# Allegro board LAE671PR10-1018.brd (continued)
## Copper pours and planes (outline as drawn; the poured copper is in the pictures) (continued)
B+ on IN2 (solid shape): 295.99,9.2 295.99,6.13 295.89,6.03 294.48,6.03 294.33,6.18 294.33,9.16 294.52,9.35 295.84,9.35
B+ on IN3 (solid shape): 132.33,2.61 132.33,1.62 132.06,1.35 128.11,1.35 127.9,1.56 127.9,2.5 128.16,2.76 132.19,2.76
B+ on IN3 (solid shape): 159.74,2.14 159.74,1.55 159.49,1.3 157.25,1.3 156.86,1.68 156.86,2.14 157.44,2.72 159.16,2.72
B+ on IN3 (solid shape): 91.76,2.89 91.76,1.74 91.31,1.29 86.77,1.29 86.7,1.35 86.59,1.35 86.35,1.59 86.35,2.83 86.7,3.18 91.47,3.18
B+ on IN3 (solid shape): outline of 4465 points within 44.29,13.1 76.23,30.97
B+ on GND3 (solid shape): 224.76,1.91 224.76,1.5 224.64,1.38 223.1,1.38 223,1.48 223,1.83 223.32,2.15 224.51,2.15
B+ on GND3 (solid shape): 268.19,2.21 268.19,1.47 268.09,1.37 266.9,1.37 266.77,1.5 266.77,2.1 266.94,2.26 268.13,2.26
B+ on IN4 (solid shape): 281.58,36.79 281.58,33.93 280.93,33.93 280.72,34.15 280.72,36.74 280.84,36.86 281.51,36.86
B+ on IN4 (solid shape): 281.64,40.29 281.64,39.26 281.53,39.14 280.83,39.14 280.71,39.26 280.71,40.34 280.84,40.47 281.46,40.47
B+ on VCC: 63.39,14 61.61,15.78 61.58,26.43 59.78,28.23 56.05,28.23 54.78,29.5 54.78,39.43 52.34,41.87 52.34,53.17 58.06,53.17 58.97,54.08 58.97,64.27 61.9,67.2 62.06,67.2 62.19,67.32 70.02,67.32 70.03,67.19 70.39,66.88 70.42,42.07 70.42,41.94 71.7,40.66 79.62,40.66 79.97,40.27 79.97,16.79 79.52,16.34 79.51,16.34 77.56,16.34 75.25,14 ; 2 cut-outs
B+ on VCC: 167.1,35.67 163.36,39.41 163.36,52.91 167.54,57.09 170.83,57.09 171.35,56.57 171.36,56.57 171.36,35.67
B+ on VCC: 267.27,3.02 269.11,4.86 275.05,4.86 275.76,5.59 277.51,5.59 279.82,7.91 295.56,7.91 295.99,7.47 295.99,3.27 274.93,3.27 273.68,2.75 273.16,1.5 273.16,1.27 266.88,1.27 266.77,1.37 266.77,2.53
B+_1.0V on TOP (solid shape): 132.1,5.27 132.1,4.55 132.6,4.06 133.46,4.06 133.59,3.93 133.59,3.33 133.49,3.23 131.51,3.23 131.21,3.53 131.21,3.54 131.04,3.71 131.04,5.25 131.21,5.42 131.96,5.42
B+_1.0V on BOTTOM (solid shape): 132.11,5.37 132.11,4.96 132.07,4.92 132.07,4.29 132.29,4.07 132.8,4.07 132.87,4.06 132.95,4.07 133.44,4.07 133.69,4.32 133.69,4.64 133.76,4.72 135.31,4.72 135.4,4.63 135.4,2.91 134.31,1.82 131.1,1.82 130.9,2.03 130.9,3.11 130.62,3.39 129.62,3.39 129.45,3.57 129.45,4.37 129.54,4.47 130.99,4.47 131.2,4.68 131.2,5.31 131.31,5.43 132.05,5.43
B+_3V on TOP (solid shape): 54.44,27.17 54.44,24.88 54.16,24.6 54.16,22.54 53.67,22.06 52.75,22.06 52.64,22.17 52.64,27.26 52.79,27.41 54.2,27.41
B+_3V on BOTTOM (solid shape): 54.37,27.27 54.37,20.89 54.37,20.89 54.37,20.77 54.21,20.61 52.5,20.61 52.44,20.67 52.44,22.11 52.6,22.27 52.6,25.33 52.37,25.56 52.08,25.56 51.82,25.82 51.82,27.28 51.9,27.37 54.27,27.37
B+_5V on TOP (solid shape): 46.27,26.63 46.27,24.99 46.19,24.91 44.93,24.91 44.5,24.48 44.5,21.69 43.59,21.69 43.47,21.8 43.47,23.96 43.35,24.09 42.73,24.09 42.48,24.34 42.48,25.5 43.87,26.89 46,26.89
B+_5V on BOTTOM (solid shape): 46.2,26.28 46.2,24.81 46.09,24.7 44.77,24.7 44.55,24.47 44.55,23.05 44.52,23.02 44.52,21.75 44.43,21.67 43.58,21.67 43.33,21.92 43.33,23.62 43.31,23.64 43.31,23.77 43.13,23.95 42.55,23.95 42.03,24.46 41.67,24.46 41.65,24.47 40.98,24.47 40.91,24.54 40.91,26.02 40.96,26.07 43,26.07 43.21,26.28 43.21,26.5 43.51,26.8 45.68,26.8
B+_AMP on TOP (solid shape): 276.45,6.01 276.45,5.29 276.26,5.1 275.19,5.1 274.95,4.86 274.66,4.86 274.64,4.88 274.64,5.69 274.69,5.74 274.79,5.74 274.85,5.68 274.85,5.52 274.85,5.51 274.85,5.17 274.89,5.13 275.02,5.13 275.08,5.2 275.08,5.44 275.24,5.6 276,5.6 276.16,5.76 276.16,6.02 276.03,6.14 275.33,6.14 275.27,6.2 275.27,6.3 275.33,6.36 276.1,6.36
B+_AMP on BOTTOM (solid shape): outline of 232 points within 267.9,2.57 277.31,14.52
B+_CAM on BOTTOM (solid shape): 282.73,33.38 282.73,30.55 282.01,29.83 281.45,29.83 280.21,28.58 280.21,27.86 280.12,27.77 278.04,27.77 277.92,27.9 277.92,28.66 278.07,28.81 278.77,28.81 280.46,30.5 280.46,30.51 280.8,30.85 280.8,33.43 280.9,33.53 282.58,33.53
B+_CAM_F on BOTTOM (solid shape): 280.24,37.7 280.24,35.46 280.3,35.39 280.28,35.27 280.31,35.14 280.31,33.75 280.15,33.59 280.15,32.65 280.11,32.61 278.73,32.61 278.58,32.77 278.58,34.9 279.23,35.56 279.23,37.8 279.31,37.88 280.06,37.88
BST_1.0V on BOTTOM (solid shape): 135.86,4.62 135.86,3.65 136.16,3.36 136.16,2.09 136.11,2.04 135.59,2.04 135.54,2.09 135.54,4.67 135.6,4.73 135.76,4.73
BST_3V on BOTTOM (solid shape): 54.25,28.36 54.25,27.59 54.2,27.54 51.92,27.54 51.84,27.62 51.84,27.74 52.48,28.38 54.23,28.38
BST_5V on TOP (solid shape): 42.97,27.3 42.97,26.41 42.88,26.32 41.94,26.32 41.72,26.54 41.72,27.49 41.89,27.65 42.62,27.65
BST_5V on BOTTOM (solid shape): 42.97,26.79 42.97,26.39 42.96,26.38 42.96,26.37 42.84,26.25 40.92,26.25 40.87,26.3 40.87,26.44 40.97,26.54 41.58,26.54 41.76,26.72 41.78,26.72 42.01,26.95 42.81,26.95
CHG_BST1 on TOP (solid shape): 65.45,16.83 65.45,16.33 65.32,16.2 64.84,16.2 64.55,15.91 64.55,14.99 64.37,14.8 64.37,14.78 64.31,14.72 64.31,13.66 64.26,13.61 64.17,13.61 64.12,13.67 64.12,15.08 64.22,15.18 64.22,16.21 64.22,16.21 64.22,16.52 64.64,16.94 65.35,16.94
CHG_BST2 on TOP (solid shape): 68.81,12.84 68.81,12.51 68.03,11.73 68.03,11.73 67.82,11.53 66.66,11.53 66.63,11.53 66.47,11.7 65.68,11.7 65.63,11.75 65.63,11.87 65.67,11.91 66.49,11.91 66.68,11.73 67.47,11.73 67.77,12.02 67.77,12.85 67.88,12.97 68.68,12.97
CHG_BST2 on BOTTOM (solid shape): 68.65,13.66 68.65,13.02 68.78,12.89 68.78,12.65 68.65,12.52 67.87,12.52 67.75,12.64 67.75,12.88 67.64,12.99 67.64,13.68 67.73,13.77 68.54,13.77
CHG_DCIN on TOP (solid shape): 62.34,14.46 62.34,14.15 62.16,13.97 61.68,13.97 61.58,13.87 61.58,13.64 61.7,13.52 62.35,13.52 62.41,13.45 62.41,13.35 62.37,13.31 61.52,13.31 61.08,13.75 61.08,14.42 61.27,14.61 62.18,14.61
CHG_LG1 on TOP (solid shape): 66.57,14.93 66.57,14.65 65.92,14.01 65.6,14.01 65.52,13.93 65.52,13.78 65.52,13.77 65.52,13.66 65.47,13.61 65.37,13.61 65.31,13.66 65.31,14.45 65.37,14.51 65.7,14.51 66.22,15.03 66.47,15.03
CHG_LG1 on BOTTOM (solid shape): 63.21,28.28 63.21,26.42 62.98,26.19 62.31,26.19 62.02,26.48 62.02,28.25 62.19,28.42 63.07,28.42
CHG_LG1 on IN2 (solid shape): 63.25,28.37 63.25,27.32 63.04,27.12 62.27,27.12 62.07,27.32 62.07,28.35 62.26,28.54 63.07,28.54
CHG_LG1 on IN2 (solid shape): 67.4,16.16 67.4,15.1 66.12,13.82 65.68,13.82 65.59,13.91 65.59,14.38 66.64,15.43 66.64,16.18 67.39,16.18
CHG_LG2 on TOP (solid shape): 67.56,14.07 67.56,13.84 66.8,13.08 66.8,13.08 66.61,12.89 65.66,12.89 65.62,12.93 65.62,13.08 65.66,13.11 66.52,13.11 66.66,13.26 66.66,13.6 67.02,13.96 67.02,14.03 67.17,14.18 67.45,14.18
CHG_LG2 on BOTTOM (solid shape): 69.69,21.1 69.69,20.71 69.6,20.62 68.2,20.62 68.12,20.7 68.12,21.23 68.23,21.33 69.46,21.33
CHG_LG2 on IN2 (solid shape): 69.46,20.77 69.46,20.33 69.1,19.97 68.87,19.97 68.05,20.8 68.05,21.28 68.16,21.39 68.84,21.39
CHG_LG2 on IN2 (solid shape): 68.47,15.4 68.47,14.66 67.07,13.26 66.72,13.26 66.6,13.38 66.6,13.79 67.71,14.9 67.71,15.42 67.83,15.55 68.32,15.55
CHG_LX1 on TOP (solid shape): 66.94,27.67 66.94,22.35 66.47,21.88 63.76,21.88 62.54,23.1 58.75,23.1 58.56,23.29 58.56,25.41 58.57,25.41 58.57,25.79 58.64,25.86 61.5,25.86 62.14,25.22 63.78,25.22 64.26,25.7 64.26,27.82 64.53,28.09 66.52,28.09
CHG_LX1 on TOP (solid shape): 66.62,16.85 66.62,16.77 66.63,16.76 66.63,15.7 65.57,14.64 65.36,14.64 65.36,14.63 65.32,14.63 65.12,14.44 65.12,13.65 65.08,13.6 64.97,13.6 64.91,13.67 64.91,14.58 65.21,14.88 65.21,14.97 65.83,15.59 65.83,15.99 65.73,16.09 65.73,16.77 65.74,16.77 65.74,16.87 65.75,16.89 66.59,16.89
CHG_LX1 on BOTTOM (solid shape): 67.39,28.26 67.72,28.26 68.04,27.95 68.04,22.12 67.79,21.88 64.17,21.88 64.17,21.88 63.74,21.88 62.54,23.08 58.73,23.08 58.55,23.26 58.55,25.81 58.62,25.89 63.02,25.89 63.51,26.38 63.51,28.09 63.69,28.26 67.39,28.26
CHG_LX1 on IN4 (solid shape): 66.93,23.43 66.93,21.97 66.82,21.85 65.95,21.85 65.89,21.91 65.89,23.5 65.97,23.58 66.78,23.58
CHG_LX1 on IN4 (solid shape): 66.22,17.12 66.62,17.12 66.66,17.08 66.66,15.74 65.6,14.68 65.38,14.68 65.3,14.77 65.3,14.97 65.3,14.97 65.3,15.07 65.9,15.67 65.9,17.01 66,17.12 66.22,17.12
CHG_LX2 on TOP (solid shape): 71.92,27.77 71.92,25.19 72.54,24.57 72.54,17.72 72.42,17.6 70.07,17.6 70,17.66 70,21.11 69.41,21.71 69.41,27.59 69.81,28 71.69,28
CHG_LX2 on TOP (solid shape): 69.18,14.94 69.18,14.33 68.73,13.88 68.42,13.88 67.53,12.98 67.53,12.98 67.41,12.87 67.19,12.87 66.82,12.5 66.65,12.5 65.64,12.5 65.62,12.52 65.62,12.68 65.65,12.71 66.63,12.71 68.53,14.61 68.53,14.88 68.68,15.04 69.08,15.04
CHG_LX2 on BOTTOM (solid shape): 72.73,27.73 72.73,17 70.09,17 70.03,17.06 70.03,21.11 68.57,22.57 68.57,27.78 69.2,28.41 72.05,28.41
CHG_LX2 on BOTTOM (solid shape): 69.82,14.32 69.82,13.14 69.8,13.13 68.99,13.13 68.92,13.19 68.92,13.75 68.52,14.16 68.52,14.69 68.87,15.05 69.09,15.05
CHG_LX2 on IN4 (solid shape): 69.18,15.53 69.18,14.15 69.03,13.99 68.55,13.99 68.5,14.04 68.5,15.66 68.51,15.67 69.05,15.67
CHG_UG1 on TOP (solid shape): 65.69,15.9 65.69,15.69 64.99,14.99 64.99,14.85 64.74,14.6 64.74,13.63 64.69,13.58 64.55,13.58 64.49,13.63 64.49,14.75 64.73,14.98 64.73,15.52 64.94,15.73 64.94,15.73 65.21,16 65.59,16
CHG_UG1 on BOTTOM (solid shape): 64.04,21.09 64.04,20.68 63.87,20.52 62.33,20.52 62.16,20.7 62.16,21.05 62.35,21.24 63.88,21.24
CHG_UG1 on IN4 (solid shape): 64.03,21.06 64.03,20.28 63.66,19.91 63.16,19.91 62.96,20.1 62.96,20.99 63.15,21.18 63.91,21.18
CHG_UG1 on IN4 (solid shape): 65.22,17.04 65.22,16.33 65.67,15.88 65.67,15.67 65.19,15.19 64.78,15.19 64.4,15.57 64.4,17.06 64.57,17.23 65.02,17.23
CHG_UG2 on TOP (solid shape): 67.62,12.53 67.62,12.12 67.36,11.86 66.8,11.86 66.64,12.01 66.64,12.05 66.61,12.09 65.68,12.09 65.61,12.16 65.61,12.29 65.64,12.31 66.65,12.31 66.7,12.37 66.89,12.37 66.91,12.38 66.92,12.38 67.24,12.7 67.45,12.7
CHG_UG2 on BOTTOM (solid shape): 75.33,21.79 75.33,20.74 75.2,20.61 74.84,20.61 74.65,20.8 74.65,21.1 74.18,21.57 74.18,21.8 74.3,21.91 75.21,21.91
CHG_UG2 on IN2 (solid shape): 75.29,21.75 75.29,20.92 75.17,20.81 74.31,20.81 74.18,20.94 74.18,21.89 74.27,21.98 75.06,21.98
CHG_UG2 on IN2 (solid shape): 67.79,12.31 68.88,12.31 68.88,12.3 68.88,11.66 68.65,11.44 67.53,11.44 67.18,11.79 66.71,11.79 66.61,11.89 66.61,12.29 66.71,12.39 66.89,12.39 67.2,12.7 67.4,12.7
CHG_VDDP on TOP (solid shape): 67.06,14.51 67.13,14.51 67.16,14.48 67.16,14.41 66.86,14.1 66.86,13.99 66.51,13.64 66.51,13.39 66.51,13.36 66.45,13.3 65.69,13.3 65.62,13.37 65.62,13.45 65.8,13.63 66.01,13.63 66.23,13.85 66.23,14.09 66.78,14.63 66.94,14.63
HP2_D_L on BOTTOM (solid shape): 281.1,63.79 281.1,63.7 280.59,63.18 279.35,63.18 279.29,63.23 279.29,63.33 279.34,63.38 280.32,63.38 280.83,63.89 281,63.89
LDO_1.0V on BOTTOM (solid shape): 137.3,8.96 137.3,7.15 136.86,6.71 136.86,6.23 136.77,6.14 135.98,6.14 135.9,6.21 135.9,6.82 136.42,7.34 136.42,8.98 136.49,9.04 137.22,9.04
LX_1.0V on BOTTOM (solid shape): 133.67,4.99 133.67,4.85 133.63,4.8 133.48,4.8 133.29,4.61 133.29,4.34 133.15,4.21 132.53,4.21 132.25,4.48 132.25,4.84 132.47,5.05 133.61,5.05
LX_1.0V on BOTTOM (solid shape): 142.54,4.82 142.54,2.23 142.07,1.76 138.58,1.76 137.71,2.63 137.24,2.63 136.04,3.83 136.04,4.66 135.89,4.8 135.89,5.42 135.97,5.5 141.86,5.5
LX_1.0V on IN2 (solid shape): 132.33,5.1 132.46,5.08 132.6,5.1 137.27,5.1 137.43,4.94 137.43,4.36 137.11,4.04 132.4,4.04 132.17,4.28 132.17,4.95 132.32,5.1
LX_1V_PRIM on TOP (solid shape): 73.85,33.34 73.85,32.7 73.81,32.66 72.82,32.66 72.29,33.19 72.29,33.55 72.43,33.69 73.49,33.69
LX_1V_PRIM on BOTTOM (solid shape): 75.91,33.53 75.91,31.28 75.82,31.2 73.01,31.2 72.95,31.26 72.95,32.32 72.27,32.99 71.48,32.99 71.41,33.06 71.41,33.72 71.46,33.77 75.67,33.77
LX_3V on TOP (solid shape): 53.33,32.35 53.33,30.35 52.9,29.92 52.59,29.92 51.94,30.57 51.94,32.3 52.25,32.61 53.08,32.61
LX_3V on BOTTOM (solid shape): 52.05,25.41 52.27,25.41 52.43,25.25 52.43,24.55 52.42,24.53 52.42,24.44 52.26,24.29 51.87,24.29 51.51,24.66 51.51,25.51 51.61,25.61 51.85,25.61
LX_3V on BOTTOM (solid shape): 54.23,31.26 54.23,28.76 54.15,28.68 52.58,28.68 51.76,27.86 51.09,27.86 51.03,27.91 51.03,28.03 51.04,28.03 51.04,29.85 50.91,29.98 49.46,29.98 49.45,29.99 49.2,29.99 48.99,30.19 48.99,32.08 49.17,32.26 53.23,32.26
LX_3V on IN2 (solid shape): 52.61,25.79 52.61,24.54 52.33,24.25 51.8,24.25 51.59,24.47 51.59,25.88 51.75,26.04 52.36,26.04
LX_3V on IN2 (solid shape): 53.67,30.63 53.67,30.42 52.88,29.63 52.87,29.63 52.55,29.31 52.54,29.31 52.51,29.27 52.51,29.04 52.39,28.92 51.93,28.92 51.76,29.09 51.76,30.06 52.61,30.91 53.39,30.91
LX_5V on TOP (solid shape): 43.8,32 43.8,30.86 43.38,30.44 41.22,30.44 41.15,30.5 41.15,32.18 41.2,32.23 43.57,32.23
LX_5V on BOTTOM (solid shape): 40.93,24.29 41.87,24.29 42.14,24.03 42.14,24.03 42.14,23.71 41.94,23.51 40.62,23.51 40.58,23.55 40.58,24.24 40.59,24.25 40.59,24.32 40.66,24.4 40.82,24.4
LX_5V on BOTTOM (solid shape): 44.92,31.72 44.92,28.38 44.53,27.99 42.48,27.99 41.64,27.14 41.64,26.9 41.42,26.67 40.84,26.67 40.73,26.55 40.22,26.55 40.12,26.64 40.12,27.46 40.17,27.52 40.7,27.52 40.91,27.72 40.91,29.18 40.75,29.33 40.75,31.83 41.15,32.23 44.41,32.23
LX_5V on IN1 (solid shape): 42.27,24.23 42.27,23.84 42.05,23.62 40.94,23.62 40.71,23.86 40.71,24.17 41.02,24.48 42.02,24.48
LX_5V on IN1 (solid shape): 43.84,32.09 43.84,31.69 43.63,31.47 42.52,31.47 42.28,31.71 42.28,32.02 42.6,32.34 43.59,32.34
LX_DDR on BOTTOM (solid shape): 124.07,7.63 124.07,5 125.03,4.04 125.03,2.31 124.92,2.19 122.87,2.19 122.79,2.27 122.79,3.39 122.62,3.55 122.18,3.55 119.97,5.76 118.36,5.76 118.36,7.07 118.38,7.09 121.2,7.09 121.91,7.8 123.89,7.8
LX_PRIM on BOTTOM (solid shape): 154.74,73.15 154.74,72.66 154.85,72.55 155.61,72.55 155.85,72.31 155.85,71.7 156.04,71.51 156.89,71.51 156.96,71.43 156.96,71.32 156.96,71.31 156.96,70.82 156.9,70.75 155.52,70.75 155.34,70.93 152.51,70.93 152.43,71.01 152.43,72.31 152.83,72.71 153.51,72.71 153.65,72.86 153.65,73.2 153.75,73.3 154.59,73.3
LX_VCC_EDRAM on TOP (solid shape): 64.55,33.95 64.55,32.62 64.36,32.43 63.69,32.43 63.48,32.64 63.48,33.95 63.54,34.01 64.49,34.01
LX_VCC_EDRAM on BOTTOM (solid shape): 65.09,33.83 65.09,32.5 64.64,32.06 64.64,31.71 62.22,31.71 62.13,31.79 62.13,32.83 61.74,33.22 60.74,33.22 60.69,33.27 60.69,33.9 60.78,33.99 64.93,33.99
LX_VCCIO on BOTTOM (solid shape): 160.41,56.5 160.41,56.03 160.66,55.79 161.55,55.79 161.65,55.68 161.65,54.95 161.6,54.9 160.19,54.9 160.18,54.89 157.54,54.89 156.83,54.18 156.2,54.18 156.11,54.27 156.11,55.58 156.22,55.7 156.87,55.7 157.01,55.84 157.01,56.37 157.31,56.66 160.26,56.66
MIC2_VREFO_L on BOTTOM (solid shape): 282.67,63.43 282.61,63.38 281.47,63.38 280.89,62.8 279.34,62.8 279.29,62.85 279.29,62.92 279.34,62.97 280.66,62.97 281.62,63.94 282.67,63.94
MIC2_VREFO_R on BOTTOM (solid shape): 281.5,62.82 281.5,62.69 281.12,62.31 280.74,62.31 280.66,62.39 279.34,62.39 279.29,62.44 279.29,62.52 279.34,62.57 280.89,62.57 281.22,62.9 281.42,62.9
MIC2_VREFO_R on IN4 (solid shape): 282.64,61.78 282.64,61.55 282.54,61.45 281.68,61.45 280.68,62.44 280.68,62.69 280.89,62.9 281.52,62.9
MUX_C_CC1 on TOP (solid shape): 289.75,49.63 289.75,49.46 289.67,49.37 288.6,49.37 288.13,48.91 288.05,48.91 287.48,48.34 286.98,48.34 286.83,48.19 286.42,48.19 286.42,48.2 286.35,48.2 286.31,48.24 286.31,48.68 286.38,48.74 287.49,48.74 288.48,49.73 289.65,49.73
MUX_C_CC1 on BOTTOM (solid shape): 289.47,20.71 289.47,20 289.65,19.82 289.65,19.5 289.3,19.16 289.3,19.1 289.27,19.07 289.27,18.34 289.27,18.2 289.18,18.11 288.99,18.11 288.87,18.23 288.87,18.9 288.94,18.97 288.94,20.1 288.77,20.26 288.77,20.73 288.8,20.75 288.83,20.78 288.86,20.81 289.37,20.81
MUX_C_CC1 on IN1 (solid shape): 287.55,21.21 288.43,21.21 288.67,20.97 288.67,20.58 288.5,20.41 287.6,20.41 287.06,20.95 287.06,21.3 287.09,21.32 287.44,21.32
MUX_C_CC2 on BOTTOM (solid shape): 290.26,44 290.26,43.77 290.25,43.74 289.93,43.43 289.93,42.92 289.82,42.81 289.59,42.81 289.41,42.98 289.41,43.8 289.63,44.01 289.66,44.04 289.69,44.07 289.76,44.15 290.11,44.15
MUX_C_VBUS_L on TOP (solid shape): 292.55,18.19 292.55,18.19 293.21,17.54 293.8,17.54 293.84,17.5 293.84,15.17 293.66,14.99 291.62,14.99 290.74,14.11 290.74,13.24 290.38,12.88 289.43,12.88 289.28,13.03 289.28,14.84 289.29,14.88 289.32,14.89 289.56,15.04 289.55,15.32 289.53,15.35 290.91,16.73 290.91,17.19 290.9,17.2 290.9,17.95 290.94,17.99 290.94,18.46 291.06,18.58 292.16,18.58
MUX_C_VBUS_L on BOTTOM (solid shape): 289.68,14.41 289.68,13.7 289.89,13.49 290.53,13.49 290.61,13.41 290.61,13 290.5,12.89 289.48,12.89 289.28,13.09 289.28,14.42 289.31,14.45 289.63,14.45
MUX_C_VBUS_L on BOTTOM (solid shape): 292.02,18.53 292.02,18.19 291.08,17.24 289.91,17.24 289.77,17.38 289.77,17.39 289.7,17.51 289.59,17.57 289.58,17.57 289.39,17.76 289.39,17.89 289.47,17.96 289.64,17.96 289.82,18.14 289.82,18.32 290.02,18.51 290.18,18.51 290.48,18.81 291.75,18.81
Net_94 on TOP (solid shape): 111.02,4.36 103.02,4.36 103.02,12.36 111.02,12.36
PD1_LPS2 on BOTTOM (solid shape): 38.88,16.71 41.04,16.71 41.18,16.57 41.18,13.98 40.71,13.52 38.2,13.52 37.79,13.1 37.79,12.01 37.67,11.89 35.32,11.89 35.23,11.98 35.23,15.73 35.5,15.99 35.5,17.51 35.54,17.55 38.04,17.55
PD2_LPS2 on BOTTOM (solid shape): 45.75,17.01 48.19,17.01 48.42,16.78 48.42,13.75 48.19,13.52 45.56,13.52 44.97,12.93 44.97,12.27 44.69,12 42.03,12 41.77,12.25 41.77,16.08 41.78,16.09 41.8,16.21 41.78,16.34 41.77,16.35 41.77,17.02 42.03,17.28 45.48,17.28
PD3_LPS2 on BOTTOM (solid shape): 192.15,7.83 192.15,5.4 190.22,3.48 190.22,2.09 190,1.87 187.26,1.87 186.77,2.35 186.77,2.66 186.77,2.67 186.77,7.88 186.87,7.97 192.01,7.97
PWM2_PH on TOP (solid shape): 69.56,51.01 69.56,48.88 69.52,48.84 67.91,48.84 67.87,48.88 67.87,50.68 68.37,51.18 69.39,51.18
PWM2_PH on BOTTOM (solid shape): 72.26,51.98 72.26,50.67 72.32,50.62 72.86,50.62 72.91,50.67 72.91,51.71 73.43,52.23 73.43,52.52 73.56,52.64 75.07,52.64 75.07,52.64 75.52,52.64 75.66,52.5 75.66,50.36 74.95,49.66 73.99,49.66 73.9,49.57 73.9,49.11 73.99,49.02 74.9,49.02 75.22,48.71 75.22,47.71 74.92,47.4 70.32,47.4 67.76,49.97 67.76,51.82 67.78,51.83 67.78,51.97 68.23,52.43 68.98,52.43 69.29,52.73 71.51,52.73
RING2 on BOTTOM (solid shape): 283.5,63.02 283.5,62.55 283.32,62.36 282.18,62.36 281.8,61.98 279.34,61.98 279.29,62.03 279.29,62.11 279.34,62.16 281.19,62.16 282.13,63.1 283.43,63.1
RING2_R on BOTTOM (solid shape): 293.05,69.56 293.05,65.7 292.79,65.44 292.16,65.44 292.1,65.38 292.1,64.65 291.99,64.54 291.06,64.54 290.93,64.66 290.93,66.34 290.94,66.34 290.94,66.53 291.33,66.92 291.33,69.55 291.42,69.64 292.97,69.64
RING2_R on IN3 (solid shape): 292.86,68.68 292.86,66.85 292.53,66.52 291.67,66.52 291.34,66.85 291.34,68.52 291.72,68.9 292.64,68.9
RING2_R on IN3 (solid shape): 286.4,65.31 286.4,65.11 286.5,65.01 286.5,64.09 286.3,63.89 285.13,63.89 284.55,63.3 284.09,63.3 283.86,63.53 283.86,64.7 284.57,65.41 286.3,65.41
RING2_R on GND3 (solid shape): 292.76,68.67 292.76,68.48 292.22,67.94 291.53,67.94 291.38,68.09 291.38,68.65 291.53,68.8 292.63,68.8
RING2_R on GND3 (solid shape): 284.65,63.96 284.65,63.58 284.37,63.3 283.73,63.3 283.58,63.46 283.58,63.94 283.61,63.99 283.88,64.27 284.34,64.27
SA_B+ on TOP (solid shape): 54.78,47.84 54.52,47.58 51.47,47.58 51.32,47.74 51.32,48.81 51.36,48.85 54.78,48.85
SA_B+ on BOTTOM (solid shape): 59.78,49.77 59.78,49.26 59.6,49.08 57.85,49.08 57.62,48.85 57.62,48.44 57.44,48.27 56.86,48.27 56.83,48.29 56.15,48.29 55.95,48.09 55.95,47.58 54.15,47.58 54.1,47.63 53.57,47.63 53.52,47.58 52.72,47.58 52.69,47.56 52.69,46.47 52.69,46.47 52.69,46.25 52.41,45.98 50.73,45.98 50.62,46.08 50.62,46.4 50.33,46.69 50.33,48.9 50.48,49.05 56,49.05 56,48.77 56.2,48.57 56.81,48.57 57.06,48.83 57.06,49.44 57.42,49.79 59.76,49.79
SD_REG2 on BOTTOM (solid shape): 290.27,37.25 290.27,36.52 290,36.26 290,35.52 289.92,35.44 289.85,35.44 289.78,35.52 289.78,36.35 289.87,36.45 289.87,36.46 289.93,36.76 289.73,37 289.72,37.01 289.72,37.35 289.77,37.4 290.13,37.4
SLEEVE on BOTTOM (solid shape): 282.08,61.3 283.43,61.3 283.58,61.14 283.58,60.71 283.38,60.51 281.88,60.51 280.81,61.58 279.31,61.58 279.26,61.63 279.26,61.68 279.36,61.78 281.6,61.78
SLEEVE_R on BOTTOM (solid shape): 286.02,63.47 286.02,62.31 285.44,61.74 285.2,61.74 285.2,61.74 285.09,61.74 284.93,61.91 284.67,61.91 284.5,61.74 284.38,61.74 284.37,61.73 284.19,61.55 283.02,61.55 283.02,62.11 283.44,62.11 284.99,63.65 285.83,63.65
SLEEVE_R on BOTTOM (solid shape): 290.68,66.72 290.68,63.83 290.34,63.48 290.34,62.39 290.34,62.39 290.34,62.29 290.27,62.22 290.03,62.22 289.97,62.28 289.97,65.27 289.76,65.48 288.76,65.48 288.58,65.31 288.58,64.31 288.32,64.05 286.11,64.05 286.03,63.96 286.03,62.91 285.76,62.64 284.72,62.64 284.48,62.88 284.48,65.04 284.79,65.35 285.94,65.35 286.2,65.61 286.83,65.61 288.17,66.95 290.46,66.95
SNUB_1V_PRIM on TOP (solid shape): 73.86,34.71 73.86,34.08 73.83,34.05 71.94,34.05 71.87,34.12 71.87,34.69 71.96,34.78 73.8,34.78
SNUB_CHG1 on TOP (solid shape): 63.72,27.06 63.72,25.48 63.64,25.41 62.31,25.41 61.79,25.93 61.79,26.83 62.07,27.11 63.67,27.11
SNUB_CHG2 on TOP (solid shape): 68.92,22.49 68.65,22.21 67.67,22.21 67.44,22.44 67.44,24.82 67.46,24.85 68.92,24.85
SNUB_VCC_EDRAM on TOP (solid shape): 62.91,33.37 62.91,31.61 62.87,31.57 62.24,31.57 62.18,31.63 62.18,33.26 62.3,33.38 62.9,33.38
SPK_OUT_L+ on TOP (solid shape): 285.15,9.34 288.64,9.34 288.74,9.23 288.74,8.79 288.74,8.78 288.74,8.6 288.59,8.45 284.53,8.45 283.37,9.61 279.85,9.61 279.76,9.7 279.76,10.58 279.83,10.64 283.86,10.64
SPK_OUT_L+ on BOTTOM (solid shape): 288.87,9.18 288.87,6.09 287.11,4.33 282.54,4.33 282.23,4.63 282.23,5.01 282.36,5.14 286.4,5.14 287.65,6.39 287.65,9.28 287.73,9.36 288.7,9.36
SPK_OUT_L+ on IN3 (solid shape): 288.74,9.33 288.74,8.66 288.52,8.44 286.54,8.44 286.34,8.65 286.34,9.29 286.6,9.56 288.51,9.56
SPK_OUT_L+ on IN3 (solid shape): 273.96,6.18 273.96,6.17 273.99,5.94 274.15,5.78 274.21,5.76 274.26,5.75 274.31,5.74 274.31,5.42 274.28,5.39 270.99,5.39 270.99,5.4 269.85,5.4 269.67,5.57 269.67,6.15 269.91,6.39 273.96,6.39
SPK_OUT_L+ on GND3 (solid shape): 269.74,6.63 269.96,6.44 270.25,6.47 270.64,6.47 270.83,6.28 270.83,6.03 270.68,5.87 269.64,5.87 269.33,6.18 269.33,6.57 269.46,6.7 269.67,6.7
SPK_OUT_L+_R on TOP (solid shape): 269.68,6.63 269.68,6.14 269.24,5.71 269.24,5.58 269.11,5.44 268.86,5.44 268.76,5.55 268.76,5.81 268.94,5.99 269.06,5.99 269.19,6.12 269.19,6.37 269.02,6.54 268.16,6.54 268.11,6.6 268.11,6.68 268.17,6.75 269.56,6.75
SPK_OUT_L+_R on BOTTOM (solid shape): 268.97,6.64 268.97,6.08 269.24,5.81 269.24,5.44 269.19,5.39 268.85,5.39 268.45,5.79 267.69,5.79 267.41,6.06 267.41,6.65 267.5,6.74 268.87,6.74
SPK_OUT_L- on TOP (solid shape): 283.22,12.98 283.22,12.62 283.36,12.48 284.34,12.48 286.35,10.48 286.35,9.78 286.35,9.77 286.35,9.69 286.28,9.62 285.28,9.62 283.24,11.65 282.28,11.65 282.28,13.07 282.29,13.08 283.12,13.08
SPK_OUT_L- on BOTTOM (solid shape): 287.34,9.52 287.34,6.56 286.2,5.42 282.35,5.42 282.24,5.54 282.24,5.83 282.38,5.97 285.29,5.97 286.12,6.8 286.12,8.6 285.23,9.49 285.23,9.86 285.37,10 286.86,10
SPK_OUT_L- on IN3 (solid shape): 286.35,10.89 286.35,9.72 286.19,9.56 285.12,9.56 284.69,9.99 283.86,9.99 283.64,10.21 283.64,10.75 283.93,11.03 286.21,11.03
SPK_OUT_L- on IN3 (solid shape): outline of 89 points within 270.68,6.99 276.89,9.78
SPK_OUT_L- on GND3 (solid shape): 271.25,7.73 271.42,7.73 271.71,7.43 271.71,7.22 271.63,7.14 271.35,7.14 271.29,7.2 270.18,7.2 270.11,7.27 270.11,7.65 270.25,7.79 270.71,7.79 270.83,7.91 271.07,7.91
SPK_OUT_R+ on TOP (solid shape): 284.55,6.59 284.55,5.33 284.06,4.84 278.79,4.84 278.67,4.96 278.67,5.52 278.67,5.53 278.67,5.75 278.79,5.86 279.24,5.86 279.35,5.75 280.28,5.75 280.39,5.86 281.52,5.86 281.68,5.7 282.14,5.7 282.31,5.86 282.59,5.86 283.45,6.72 284.42,6.72
SPK_OUT_R+ on BOTTOM (solid shape): 284.4,6.75 284.51,6.63 284.51,6.38 284.38,6.24 282.38,6.24 282.23,6.39 282.23,6.64 282.33,6.75 284.31,6.75
SPK_OUT_R+ on IN2 (solid shape): 272.43,1.98 272.43,1.54 272.17,1.28 269.95,1.28 269.85,1.39 269.85,2.08 270.06,2.3 272.11,2.3
SPK_OUT_R+ on IN2 (solid shape): 284.5,6.67 284.5,5.22 283.98,4.7 283.97,4.7 283.24,3.96 282.86,3.96 282.5,4.33 282.5,5.69 283.55,6.74 284.43,6.74
SPK_OUT_R+_R on TOP (solid shape): 270.04,5.71 270.04,4.43 270.04,4.43 270.04,4.02 270.14,3.92 270.14,2.39 269.59,2.39 269.57,2.41 269.57,4.19 269.84,4.46 269.84,5.69 269.89,5.74 270.01,5.74
SPK_OUT_R- on TOP (solid shape): 284.24,8.22 284.24,7.84 284.27,7.81 285.08,7.81 285.43,8.16 285.72,8.16 286.09,7.79 286.09,7.12 285.98,7 283.11,7 283.11,8.29 283.2,8.38 284.07,8.38
SPK_OUT_R- on BOTTOM (solid shape): 285.71,7.9 285.71,7.13 285.6,7.02 282.39,7.02 282.25,7.15 282.25,7.46 282.34,7.55 283.2,7.55 283.7,8.05 285.56,8.05
SPK_OUT_R- on IN2 (solid shape): 285.75,8.02 285.75,7.15 285.58,6.97 284.66,6.97 284.07,7.56 284.07,8 284.28,8.21 285.56,8.21
SPK_OUT_R- on IN2 (solid shape): 269.79,3.49 269.79,3.1 269.8,3.08 269.8,2.7 269.59,2.49 269.59,1.62 269.37,1.4 268.38,1.4 268.31,1.48 268.31,2.79 269.24,3.72 269.56,3.72
SPK_OUT_R- on IN2 (solid shape): outline of 85 points within 272.73,4.61 277.58,6.37
SPK_OUT_R-_R on TOP (solid shape): 269.65,5.67 269.65,4.58 269.22,4.15 269.22,3.94 269.22,3.93 269.22,2.4 268.61,2.4 268.61,4.26 269.42,5.06 269.42,5.67 269.48,5.73 269.58,5.73
SW_1.8VA on BOTTOM (solid shape): 157.81,62.6 157.86,62.6 158.59,62.6 158.75,62.44 158.75,61.23 158.03,60.5 154.26,60.5 154.11,60.65 154.11,61.14 153.82,61.43 152.92,61.43 152.77,61.59 152.77,62.52 152.85,62.6
SW_1.8VU on BOTTOM (solid shape): 157.6,12.79 157.6,11.32 157.6,11.31 157.6,9.74 157.66,9.67 157.66,9.24 157.88,9.03 157.88,8.52 157.31,7.95 157.31,7.04 157.24,6.97 156.12,6.97 156.06,7.03 156.06,8 156.05,8 156.05,8.86 156.05,8.87 156.05,11.36 156.05,11.37 156.05,12.86 156.22,13.02 157.37,13.02
TBT_A_CC1 on IN1 (solid shape): 5.97,46.18 5.97,45.98 5.91,45.92 5.47,45.92 5.35,45.81 5.35,45.77 5.3,45.62 5.35,45.46 5.35,45.12 5.21,44.98 4.8,44.98 4.65,45.13 4.65,46.25 4.86,46.46 5.69,46.46
TBT_A_CC1 on IN4 (solid shape): 7.96,40.32 7.96,40.01 7.96,40.01 7.96,39.2 7.88,39.13 7.18,39.13 7.02,39.28 7.02,40.34 7.15,40.47 7.81,40.47
TBT_A_VBUS_L on TOP (solid shape): 17.73,28.75 17.73,28.74 17.8,28.63 17.91,28.56 17.92,28.56 18.06,28.42 18.06,28.21 17.74,27.9 17.74,27.9 17.68,27.86 17.65,27.84 17.51,27.7 17.28,27.64 17.14,27.45 17.1,27.41 17.1,27.28 16.56,26.75 15.97,26.75 15.88,26.65 15.88,25.52 16.18,25.22 16.18,25.17 16.19,25.16 16.19,24.47 16.02,24.29 14.88,24.29 14.8,24.36 14.8,25.18 14.66,25.33 14.66,26.74 15.31,27.39 15.92,27.39 16.11,27.58 16.12,27.58 16.42,27.63 16.57,27.9 16.57,27.92 16.73,28.08 16.73,28.16 16.76,28.19 16.76,28.29 16.98,28.51 17.16,28.51 17.34,28.68 17.34,28.86 17.41,28.94 17.54,28.94
TBT_B_CC1 on TOP (solid shape): 28.88,31.78 29.21,31.78 29.29,31.7 29.59,31.7 29.66,31.63 29.66,31.45 29.57,31.37 28.81,31.37 28.7,31.26 28.29,31.26 27.73,31.82 27.26,31.82 27.19,31.89 27.19,32.44 27.26,32.51 28.15,32.51
TBT_B_CC1 on IN1 (solid shape): 5.73,62.75 5.84,62.75 5.94,62.65 5.94,62.45 5.84,62.35 5.78,62.35 5.76,62.33 5.34,62.33 5.33,62.31 5.17,62.31 4.77,61.91 4.39,61.91 4.26,62.03 4.26,62.35 4.67,62.75 5.73,62.75
TBT_B_CC2 on TOP (solid shape): 10.38,64.59 10.38,64.17 10.3,64.09 9.11,64.09 8.61,63.6 7.23,63.6 7.13,63.69 7.13,63.85 7.22,63.93 8.16,63.93 8.74,64.51 8.88,64.6 9.01,64.7 10.27,64.7
TBT_B_CC2 on TOP (solid shape): 28.21,31.12 28.84,31.12 28.92,31.2 29.58,31.2 29.66,31.13 29.66,30.97 29.56,30.87 28.9,30.87 28.72,30.69 27.87,30.69 27.75,30.72 27.63,30.69 27.34,30.99 27.34,31.49 27.47,31.63 27.71,31.63
TBT_B_VBUS_L on TOP (solid shape): 34.96,31.66 34.96,31.02 34.76,30.81 34.13,30.81 34.06,30.88 33.49,30.88 33.39,30.97 33.39,31.15 33.5,31.25 34.13,31.25 34.32,31.45 34.32,31.69 34.45,31.82 34.8,31.82
TBT_B_VBUS_L on TOP (solid shape): 30.28,30.99 30.28,30.97 30.34,30.86 30.46,30.79 30.47,30.79 30.61,30.65 30.61,30.24 30.26,29.89 30.26,29.86 29.88,29.48 29.85,29.48 29.82,29.45 29.66,29.45 29.61,29.4 29.36,29.4 28.36,28.4 28.36,27.78 28.23,27.65 27.23,27.65 26.7,28.19 26.7,28.99 26.81,29.1 27.17,29.1 27.3,29.23 27.3,29.55 27.9,30.16 28.95,30.16 29.08,30.29 29.09,30.29 29.2,30.36 29.27,30.47 29.27,30.48 29.53,30.74 29.71,30.74 29.88,30.92 29.88,31.1 29.96,31.17 30.09,31.17
TBT_B_VBUS_L on BOTTOM (solid shape): 29.47,29 29.6,28.79 29.84,28.71 29.88,28.67 30.06,28.67 30.09,28.65 30.09,27.6 29.97,27.49 28.19,27.49 27.91,27.77 27.89,27.82 27.89,28.14 27.79,28.24 27.79,28.83 27.96,29
TBT_B_VBUS_L on IN1 (solid shape): outline of 254 points within 27.64,26.57 36.43,31.75
TBT_SVR_IND on BOTTOM (solid shape): 21.13,56.48 21.13,55.53 19.56,53.96 19.56,52.45 19.5,52.39 19.39,52.39 19.28,52.27 19.28,52.07 19.17,51.97 19.05,51.97 18.89,52.13 18.89,52.73 18.65,52.98 18.54,52.98 17.6,53.92 17.6,54.57 17.36,54.82 16.65,54.82 16.63,54.85 16.63,56.08 16.91,56.36 19.91,56.36 20.06,56.51 21.11,56.51
VCORE_B+ on TOP (solid shape): 65.6,39.81 65.95,39.46 65.95,38.69 65.83,38.56 65.32,38.56 64.68,39.2 64.05,39.2 63.92,39.33 63.92,39.58 64.17,39.83 65.58,39.83
VCORE_B+ on TOP (solid shape): outline of 398 points within 56.45,40.97 67.98,71.01
VCORE_B+ on BOTTOM (solid shape): outline of 84 points within 55.59,38.41 67.28,74
VCORE_B+ on GND1 (solid shape): 65.35,47.77 65.35,45.31 65.24,45.21 64.64,45.21 64.56,45.29 64.56,47.91 65.21,47.91
VCORE_B+ on GND1 (solid shape): 64.71,57.53 64.76,57.51 64.82,57.5 65.07,57.25 65.07,54.57 64.71,54.21 63.51,54.21 63.32,54.4 63.32,57.12 63.73,57.53
VCORE_B+ on GND3 (solid shape): 65.59,47.82 65.59,45.37 65.44,45.22 64.48,45.22 64.33,45.36 64.33,47.86 64.39,47.92 65.49,47.92
VCORE_B+ on GND3 (solid shape): 64.74,57.52 64.86,57.5 64.98,57.52 65.07,57.52 65.19,57.39 65.19,57.09 65.25,57.03 65.25,54.64 64.83,54.23 63.53,54.23 63.32,54.43 63.32,56.99 63.85,57.52
VCORE_B+ on IN4 (solid shape): outline of 553 points within 56.45,39.08 66.25,63.75
VL on BOTTOM (solid shape): 38.14,29.83 38.14,26.8 38.43,26.51 38.61,26.51 38.7,26.43 38.7,26.33 38.62,26.25 37.71,26.25 37.43,26.52 37.43,26.85 37.42,26.87 37.42,27.05 36.94,27.52 36.94,28.99 36.95,29 36.95,29.82 37.13,30 37.97,30
N17806340 on BOTTOM (solid shape): 164.26,6.89 164.26,5.04 163.76,4.53 163.76,3.37 163.66,3.27 163.38,3.27 163.37,3.28 163.28,3.28 163.25,3.24 163.25,1.94 162.91,1.6 161.51,1.6 161.41,1.7 161.41,2.48 161.61,2.67 162.06,2.67 162.19,2.81 162.19,4.18 162.2,4.25 162.19,4.32 162.19,4.66 162.45,4.91 163.03,4.91 163.22,5.1 163.22,6.81 163.41,7 164.14,7
N18537697 on BOTTOM (solid shape): 73.83,43.49 73.83,42.86 73.46,42.49 73.31,42.49 73.23,42.4 73.23,41.65 73.29,41.59 74.43,41.59 74.66,41.36 74.66,39.83 74.21,39.38 70.83,39.38 70.05,40.16 69.86,40.16 68.52,41.51 68.52,42.32 68.54,42.35 68.54,43.36 68.95,43.77 73.55,43.77
N18676885 on BOTTOM (solid shape): 41.21,8.34 41.21,7.09 40.79,6.67 39.8,6.67 39.66,6.81 39.66,7.67 39.79,7.79 40.45,7.79 40.57,7.91 40.57,8.28 40.77,8.49 41.05,8.49
N18681310 on BOTTOM (solid shape): 57.76,9.34 57.76,7.98 57.73,7.96 56.7,7.96 56.57,8.08 55.31,8.08 55.28,8.11 55.28,9.46 57.65,9.46
N18681327 on TOP (solid shape): 66.62,18.37 66.62,17.64 66.44,17.47 64.57,17.47 64.5,17.54 64.5,18.36 64.53,18.39 66.6,18.39
N18681352 on BOTTOM (solid shape): 69.8,12.29 69.8,11.75 69.75,11.7 67.78,11.7 67.69,11.78 67.69,12.28 67.77,12.35 69.74,12.35
N18681577 on BOTTOM (solid shape): 58.79,14.97 59.29,14.97 59.45,14.82 59.45,11.08 59.17,10.8 56.88,10.8 56.55,11.13 56.55,11.39 57.14,11.39 57.5,11.75 57.14,12.11 56.55,12.11 56.55,13.07 56.32,13.31 56.32,14.9 56.39,14.98 58.79,14.98
N18683466 on BOTTOM (solid shape): 55.6,29.64 55.6,27.54 54.7,27.54 54.51,27.72 54.51,28.33 54.92,28.74 54.92,29.64 54.93,29.65 55.59,29.65
N18683563 on TOP (solid shape): 43.6,30.16 43.6,28.66 42.84,27.9 41.95,27.9 41.7,28.14 41.7,28.41 41.69,28.42 41.69,29.29 42.63,30.23 43.54,30.23
N18684725 on BOTTOM (solid shape): 119.85,5.2 119.85,4.61 120.08,4.38 120.99,4.38 121.74,3.63 121.74,3.07 121.71,3.04 121.17,3.04 121.13,3.08 121.13,3.16 120.46,3.83 120.26,3.83 119.6,4.49 119.6,5.2 119.67,5.28 119.77,5.28
N18684739 on BOTTOM (solid shape): 115.47,6.57 115.47,6.24 115.84,5.87 118.02,5.87 118.02,5.49 115.81,5.49 115.13,4.81 113.78,4.81 113.55,5.04 113.55,5.96 113.46,6.05 112.96,6.05 112.85,6.15 112.85,6.85 113.07,7.07 114.97,7.07
N18684739 on GND3 (solid shape): 115.46,6.76 115.46,6.1 115.36,6 112.96,6 112.91,6.05 112.91,6.71 113.17,6.97 115.25,6.97
N18684739 on GND1: 114.99,7 113.25,7 112.89,6.65 112.89,6.34 113.02,6.22 115.41,6.22 115.48,6.29 115.48,6.51
N18686200 on BOTTOM (solid shape): 167.68,62.61 167.68,61.15 167.08,60.55 161.45,60.55 160.96,61.04 160.71,61.29 160.71,61.78 160.71,61.78 160.71,62.31 160.71,62.32 160.71,62.43 160.76,62.48 161.78,62.48 162.02,62.72 162.02,62.72 162.4,63.1 167.19,63.1
N18686705 on BOTTOM (solid shape): 156.29,4.96 156.57,4.96 156.58,4.96 156.79,4.96 156.79,4.96 157.08,4.96 157.08,4.96 157.27,4.96 157.31,4.92 157.31,3.92 157.94,3.29 157.94,2.26 157.75,2.07 152.97,2.07 152.66,2.38 152.66,3.28 152.87,3.49 155.29,3.49 155.81,4.01 155.81,4.77 156.01,4.96 156.29,4.96
N18686709 on BOTTOM (solid shape): 158.5,14.55 158.5,13.88 158.39,13.77 157.94,13.77 157.41,13.24 156.08,13.24 155.92,13.39 155.92,14.49 156.06,14.62 158.42,14.62
N18689543 on TOP (solid shape): 69.59,53.48 69.59,51.53 69.53,51.47 67.95,51.47 67.87,51.55 67.87,53.44 68.12,53.69 69.37,53.69
N18689566 on BOTTOM (solid shape): 71.67,63.16 71.67,61.75 71.6,61.69 70.56,61.69 70.47,61.6 70.47,61.12 70.54,61.06 71.55,61.06 71.63,60.98 71.63,60.03 71.63,60.02 71.63,58.3 71.1,57.78 69.93,57.78 68.14,59.57 67.2,59.57 67.2,59.57 67.2,61.55 69.01,63.37 71.46,63.37
N18690739 on TOP (solid shape): 73.19,40.33 73.19,39.34 73.13,39.28 70.47,39.28 70.39,39.36 70.39,40.25 70.51,40.36 73.15,40.36
N18759595 on BOTTOM (solid shape): 56.05,57.66 56.05,56.16 55.95,56.06 55.29,56.06 55.26,56.04 55.26,55.59 55.3,55.55 55.99,55.55 56.05,55.49 56.05,51.67 55.69,51.31 53.43,51.31 52.95,51.8 52.95,57.42 53.46,57.93 55.77,57.93
N20877664 on TOP (solid shape): 22.39,30.64 22.39,30.34 22.58,30.16 23.32,30.16 23.47,30.01 23.47,29.28 23.31,29.11 22.78,29.11 22.77,29.11 22.32,29.11 21.74,29.69 21.45,29.69 21.37,29.77 21.37,29.99 21.26,30.1 20.96,30.1 20.83,30.23 20.83,30.45 20.92,30.54 21.12,30.54 21.34,30.76 21.34,30.85 21.44,30.95 22.09,30.95
N20877810 on TOP (solid shape): 34.51,33.08 34.51,32.77 34.63,32.65 34.66,32.65 34.67,32.64 34.79,32.61 34.92,32.64 34.93,32.65 35.07,32.65 35.24,32.82 35.73,32.82 35.8,32.75 35.8,32.21 35.79,32.2 35.06,32.2 34.97,32.11 34.36,32.11 34.13,31.88 33.97,31.88 33.87,31.99 33.87,32.06 33.77,32.16 33.77,32.17 33.68,32.26 33.64,32.29 33.51,32.3 33.39,32.42 33.39,32.6 33.44,32.65 33.67,32.65 33.82,32.8 33.82,33.1 33.92,33.2 34.38,33.2
N20878169 on BOTTOM (solid shape): 288.27,14.3 288.27,14.29 288.34,14.14 288.48,14.07 288.5,14.07 288.69,13.89 288.69,13.73 289.02,13.4 289.02,13.13 288.92,13.03 287.72,13.03 287.36,13.39 287.36,13.88 287.56,14.07 287.57,14.07 287.7,14.14 287.77,14.28 287.78,14.29 287.94,14.46 288.11,14.46
N21092755 on TOP (solid shape): 20.44,8.72 20.44,7.71 20.09,7.36 20.09,5.98 20,5.9 19.62,5.9 19.39,6.13 19.39,7.54 19.66,7.81 19.66,8.97 19.82,9.13 20.02,9.13
N21092755 on IN1 (solid shape): 20.39,10.63 20.53,10.63 20.57,10.59 20.62,10.57 20.69,10.56 20.73,10.56 20.77,10.57 20.79,10.58 20.99,10.58 21.28,10.28 21.28,10.14 21.27,10.11 21.25,10.06 21.25,10.01 21.25,9.97 21.27,9.92 21.28,9.89 21.28,9.67 20.23,8.62 19.77,8.62 19.65,8.74 19.65,8.98 20.2,9.53 20.2,9.75 20.21,9.76 20.21,10.01 20.45,10.01 20.45,9.97 20.46,9.92 20.48,9.88 20.51,9.85 20.54,9.81 20.58,9.79 20.62,9.77 20.67,9.76 20.71,9.76 20.76,9.77 20.8,9.78 20.84,9.8 20.88,9.83 20.91,9.86 20.93,9.9 20.95,9.95 20.96,9.99 20.96,10.04 20.95,10.08 20.93,10.13 20.91,10.16 20.88,10.2 20.84,10.23 20.8,10.25 20.76,10.26 20.71,10.27 20.67,10.27 20.62,10.26 20.58,10.24 20.54,10.21 20.51,10.18 20.48,10.15 20.46,10.1 20.45,10.06 20.45,10.01 20.21,10.01 20.21,10.11 20.2,10.12 20.2,10.22 20.08,10.34 19.98,10.34 19.97,10.35 19.83,10.35 19.67,10.5 19.67,10.78 19.83,10.94 20.07,10.94
N24109146 on BOTTOM (solid shape): 263.92,5.53 263.92,4.27 263.9,4.25 263.64,4.25 263.63,4.26 260.02,4.26 259.82,4.46 259.82,5.95 260.05,6.18 263.27,6.18
N24110025 on BOTTOM (solid shape): 210.92,2.5 210.92,1.28 210.69,1.05 207.67,1.05 207.52,1.2 207.52,2.46 207.66,2.6 210.82,2.6
N34459429 on BOTTOM (solid shape): 278.14,59.19 278.14,58.25 278.65,57.74 280.07,57.74 280.2,57.61 280.2,56.01 280.05,55.86 279.52,55.86 279.41,55.96 279.41,56.57 277.97,58.02 277.97,59.19 278.02,59.24 278.09,59.24
N34741776 on TOP (solid shape): 277.81,13.2 277.81,12.44 277.8,12.42 276.83,12.42 275.81,13.44 275.21,13.44 275.21,13.44 275.12,13.44 274.62,12.93 274.58,12.9 274.54,12.86 274.44,12.76 274.44,12.01 274.37,11.94 274.3,11.94 274.24,12 274.24,12.83 275.43,14.02 276.99,14.02
N34768323 on TOP (solid shape): 278.66,9.61 278.66,9.17 278.6,9.11 277.22,9.11 277.06,8.95 275.29,8.95 275.24,9 275.24,9.08 275.3,9.15 276.51,9.15 276.98,9.62 278.64,9.62
N34768417 on TOP (solid shape): 274.44,5.7 274.44,4.79 274.52,4.7 275,4.7 275.26,4.96 277.48,4.96 277.61,4.83 277.61,4.32 277.59,4.31 277.22,4.31 276.78,3.87 276.46,3.87 275.88,4.44 274.43,4.44 274.23,4.64 274.23,5.7 274.27,5.73 274.41,5.73
N34768420 on TOP (solid shape): 278.67,8.73 278.67,8.22 278.64,8.19 277.76,8.19 277.76,8.19 276.98,8.19 276.63,8.54 275.29,8.54 275.23,8.6 275.23,8.68 275.29,8.75 278.66,8.75
N34949443 on BOTTOM (solid shape): 267.15,11.36 267.15,9.84 267.25,9.74 267.78,9.74 267.88,9.63 267.88,9.25 267.81,9.18 267.55,9.18 267.46,9.19 267.38,9.18 266.64,9.18 266.46,9.35 266.46,10.77 266.51,10.83 266.51,11.39 266.54,11.41 267.1,11.41
N52922958 on TOP (solid shape): 150.3,32.92 150.3,31.87 149.92,31.49 147.42,31.49 147.35,31.55 147.35,31.99 147.31,32.02 146.45,32.02 146.38,32.09 146.38,32.65 146.42,32.68 148.63,32.68 149.01,33.05 150.17,33.05
N52925836 on TOP (solid shape): 224.34,8.85 224.78,8.41 225.38,8.41 225.48,8.31 225.48,7.34 225.44,7.3 224.18,7.3 223.23,8.25 223.23,8.37 223.28,8.41 224.02,8.41 224.04,8.44 224.04,8.59 224.02,8.62 223.29,8.62 223.23,8.67 223.23,8.79 223.3,8.85 224.34,8.85
N52925896 on TOP (solid shape): 225.53,11.33 225.53,10.47 225.45,10.39 224.45,10.39 224.28,10.23 223.3,10.23 223.22,10.31 223.22,10.38 223.26,10.42 224.02,10.42 224.04,10.45 224.04,10.55 223.99,10.6 223.32,10.6 223.22,10.7 223.22,10.85 223.85,11.48 225.38,11.48
N52930519 on TOP (solid shape): 267.5,46.38 267.5,45.44 266.94,44.88 266.94,44.2 266.87,44.12 266.03,44.12 265.98,44.17 265.98,45.16 265.77,45.36 265.77,46.14 266.09,46.46 267.43,46.46
N52934489 on TOP (solid shape): 255.56,6.58 256.35,6.58 256.43,6.5 256.43,5.54 256.38,5.49 255.36,5.49 254.7,6.15 254.14,6.15 254.04,6.25 254.04,6.31 254.11,6.37 254.79,6.37 254.85,6.43 254.85,6.51 254.79,6.57 254.09,6.57 254.04,6.62 254.04,6.71 254.09,6.76 255.39,6.76
N52934545 on TOP (solid shape): 256.4,9.49 256.4,8.6 255.61,8.6 255.15,8.15 254.09,8.15 254.04,8.2 254.04,8.32 254.09,8.37 254.78,8.37 254.86,8.45 254.86,8.5 254.8,8.56 254.1,8.56 254.04,8.61 254.04,8.76 254.14,8.86 254.8,8.86 255.46,9.52 256.37,9.52
N57177583 on TOP (solid shape): 139,70.58 139,69.24 138.77,69.02 137.97,69.02 137.79,69.2 136.71,69.2 136.51,69.41 136.51,70.25 136.63,70.36 138.05,70.36 138.44,70.75 138.83,70.75
N57178338 on BOTTOM (solid shape): 149.97,13.89 150.84,13.89 150.87,13.86 150.87,13.38 150.86,13.38 150.86,13.19 150.81,13.15 149.85,13.15 149.38,13.61 147.75,13.61 147.6,13.76 147.6,14.06 147.92,14.37 149.97,14.37
N61547946 on BOTTOM (solid shape): 287.84,27.58 287.84,26.38 287.37,25.91 286.11,25.91 285.74,26.28 285.74,27.73 285.81,27.79 285.81,28.83 285.91,28.94 286.48,28.94
N64008725 on BOTTOM (solid shape): 30.9,29.19 30.95,29.15 30.94,29.1 30.91,29.07 30.91,28.18 31.1,28 31.48,28 31.66,27.82 31.66,27.06 31.49,26.89 30.77,26.89 30.42,27.24 30.42,29.13 30.48,29.19

Small or netless copper shapes (teardrops, artwork), in the pictures only: 61 on TOP, 128 on BOTTOM, 19 on IN1, 62 on GND1, 3 on IN2, 1 on IN3, 46 on GND3, 13 on IN4

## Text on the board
Ref Des/Silkscreen Bottom: B | C | A | H1 | S1 | H2 | H7 | H3 | H4 | H5 | H6 | H8 | H9 | H10
User.Comments: CR_TPS65982_1 | CR_TPS65982-2_1 | PARTITION_2 | CR_RAM_1 | CR_CPU_1 | CR_AR_1 | CR_AR-N_1 | LA-E671P | 2017-10-18 | 2018-10-18 | Monika | CAZ60
Ref Des/Silkscreen Top: R276 | R275 | R278 | R277 | S2 | S3
XSECTION_CHART: *  SURFACE - AIR 0 MIL | L1: TOP CONDUCTOR - COPPER 1.8 MIL | *  DIELECTRIC - FR-4 2.46 MIL | L2: IN1 CONDUCTOR - COPPER 1.3 MIL | *  DIELECTRIC - FR-4 2 MIL | L3: GND1 PLANE - COPPER 1.3 MIL | *  DIELECTRIC - FR-4 2.5 MIL | L4: IN2 CONDUCTOR - COPPER 0.65 MIL | *  DIELECTRIC - FR-4 3.11 MIL | L5: GND2 PLANE - COPPER 1.35 MIL | *  DIELECTRIC - FR-4 2.68 MIL | L6: VCC PLANE - COPPER 1.35 MIL | L7: IN3 CONDUCTOR - COPPER 0.65 MIL | L8: GND3 PLANE - COPPER 1.3 MIL | L9: IN4 CONDUCTOR - COPPER 1.3 MIL | L10: BOTTOM CONDUCTOR - COPPER 1.8 MIL | DESIGN CROSS SECTION CHART | ___________________________ | TOTAL THICKNESS 35.62 MIL | 1-10 | 1-3 | 1-2 | 2-3 | 3-8 | 8-9 | 8-10 | 9-10
User.38: FIGURE | SIZE | 8.0 | 16.0 | 26.0 | 71.0 | 79.0 | 102.0 | 130.0 | 28.0 | 30.0 | 31.0 | 43.0 | 63.0 | 47.0x20.0 | 49.0x28.0 | 63.0x24.0 | 75.0x24.0 | 79.0x28.0 | 33.0x26.0 | 37.0x30.0 | 67.0x47.0 | 91.0x71.0 | DRILL CHART: TOP to BOTTOM | ALL UNITS ARE IN MILS | TOLERANCE | +3.0/-3.0 | +2.0/-2.0 | PLATED | NON-PLATED | QTY | 3596 | 12 | 2 | 7 | 3 | 1 | 4
User.39: FIGURE | SIZE | 4.0 | DRILL CHART: TOP to IN1 | ALL UNITS ARE IN MILS | TOLERANCE | +1.0/-1.0 | PLATED | QTY | 512
User.40: FIGURE | SIZE | 8.0 | DRILL CHART: GND1 to GND3 | ALL UNITS ARE IN MILS | TOLERANCE | +3.0/-3.0 | PLATED | QTY | 1971
User.41: FIGURE | SIZE | 4.0 | DRILL CHART: TOP to GND1 | ALL UNITS ARE IN MILS | TOLERANCE | +1.0/-1.0 | PLATED | QTY | 1797
User.42: FIGURE | SIZE | 4.0 | DRILL CHART: GND3 to BOTTOM | ALL UNITS ARE IN MILS | TOLERANCE | +1.0/-1.0 | PLATED | QTY | 2592
User.43: FIGURE | SIZE | 4.0 | DRILL CHART: GND3 to IN4 | ALL UNITS ARE IN MILS | TOLERANCE | +1.0/-1.0 | PLATED | QTY | 366
User.44: FIGURE | SIZE | 4.0 | DRILL CHART: IN4 to BOTTOM | ALL UNITS ARE IN MILS | TOLERANCE | +1.0/-1.0 | PLATED | QTY | 407
User.45: trace Width | 3.75 | 4.5 | 2.5 | 3 | 4.5/4.5 | Width/Space | 4.25/4.75 | 3.5/10.5 | 4/5 | 3.5/11.5 | 3/12 | 4/7 | 2.5/12 | L6/L8 | L2 | L3 | L3/L5 | L8 | L9 | 0_9mm_2+6+2(50ohm) (Top IN1 G-V IN2 G-V G-V IN3 G-V IN4 Bot)-170106 | L5-GND2 | L8-GND3 | L10-BOT | L3-GND1 | L6-VCC | L7-IN3 | L4-IN2 | L9-IN4 | L2-IN1 | L1-TOP | LAYER | NAME | STACKUP:10 LAYER | 40 ohm | 50 ohm | THICKNESS=0.9mm | 72 ohm | 85 ohm | 90 ohm | 100ohm | Ref | IMPEDANCE | FIGURE | SIZE | 4.0 | DRILL CHART: IN1 to GND1 | ALL UNITS ARE IN MILS | TOLERANCE | +1.0/-1.0 | PLATED | QTY | 292
